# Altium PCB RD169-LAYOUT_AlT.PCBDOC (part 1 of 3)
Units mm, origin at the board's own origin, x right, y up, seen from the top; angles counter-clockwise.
Board outline 192 x 135 mm, 2 copper layers (TOP, BOTTOM), stack 0 mm thick; 266 components, 140 nets, 1304 pads, 0 vias.
Unrouted connection lines stored in the file: 1.
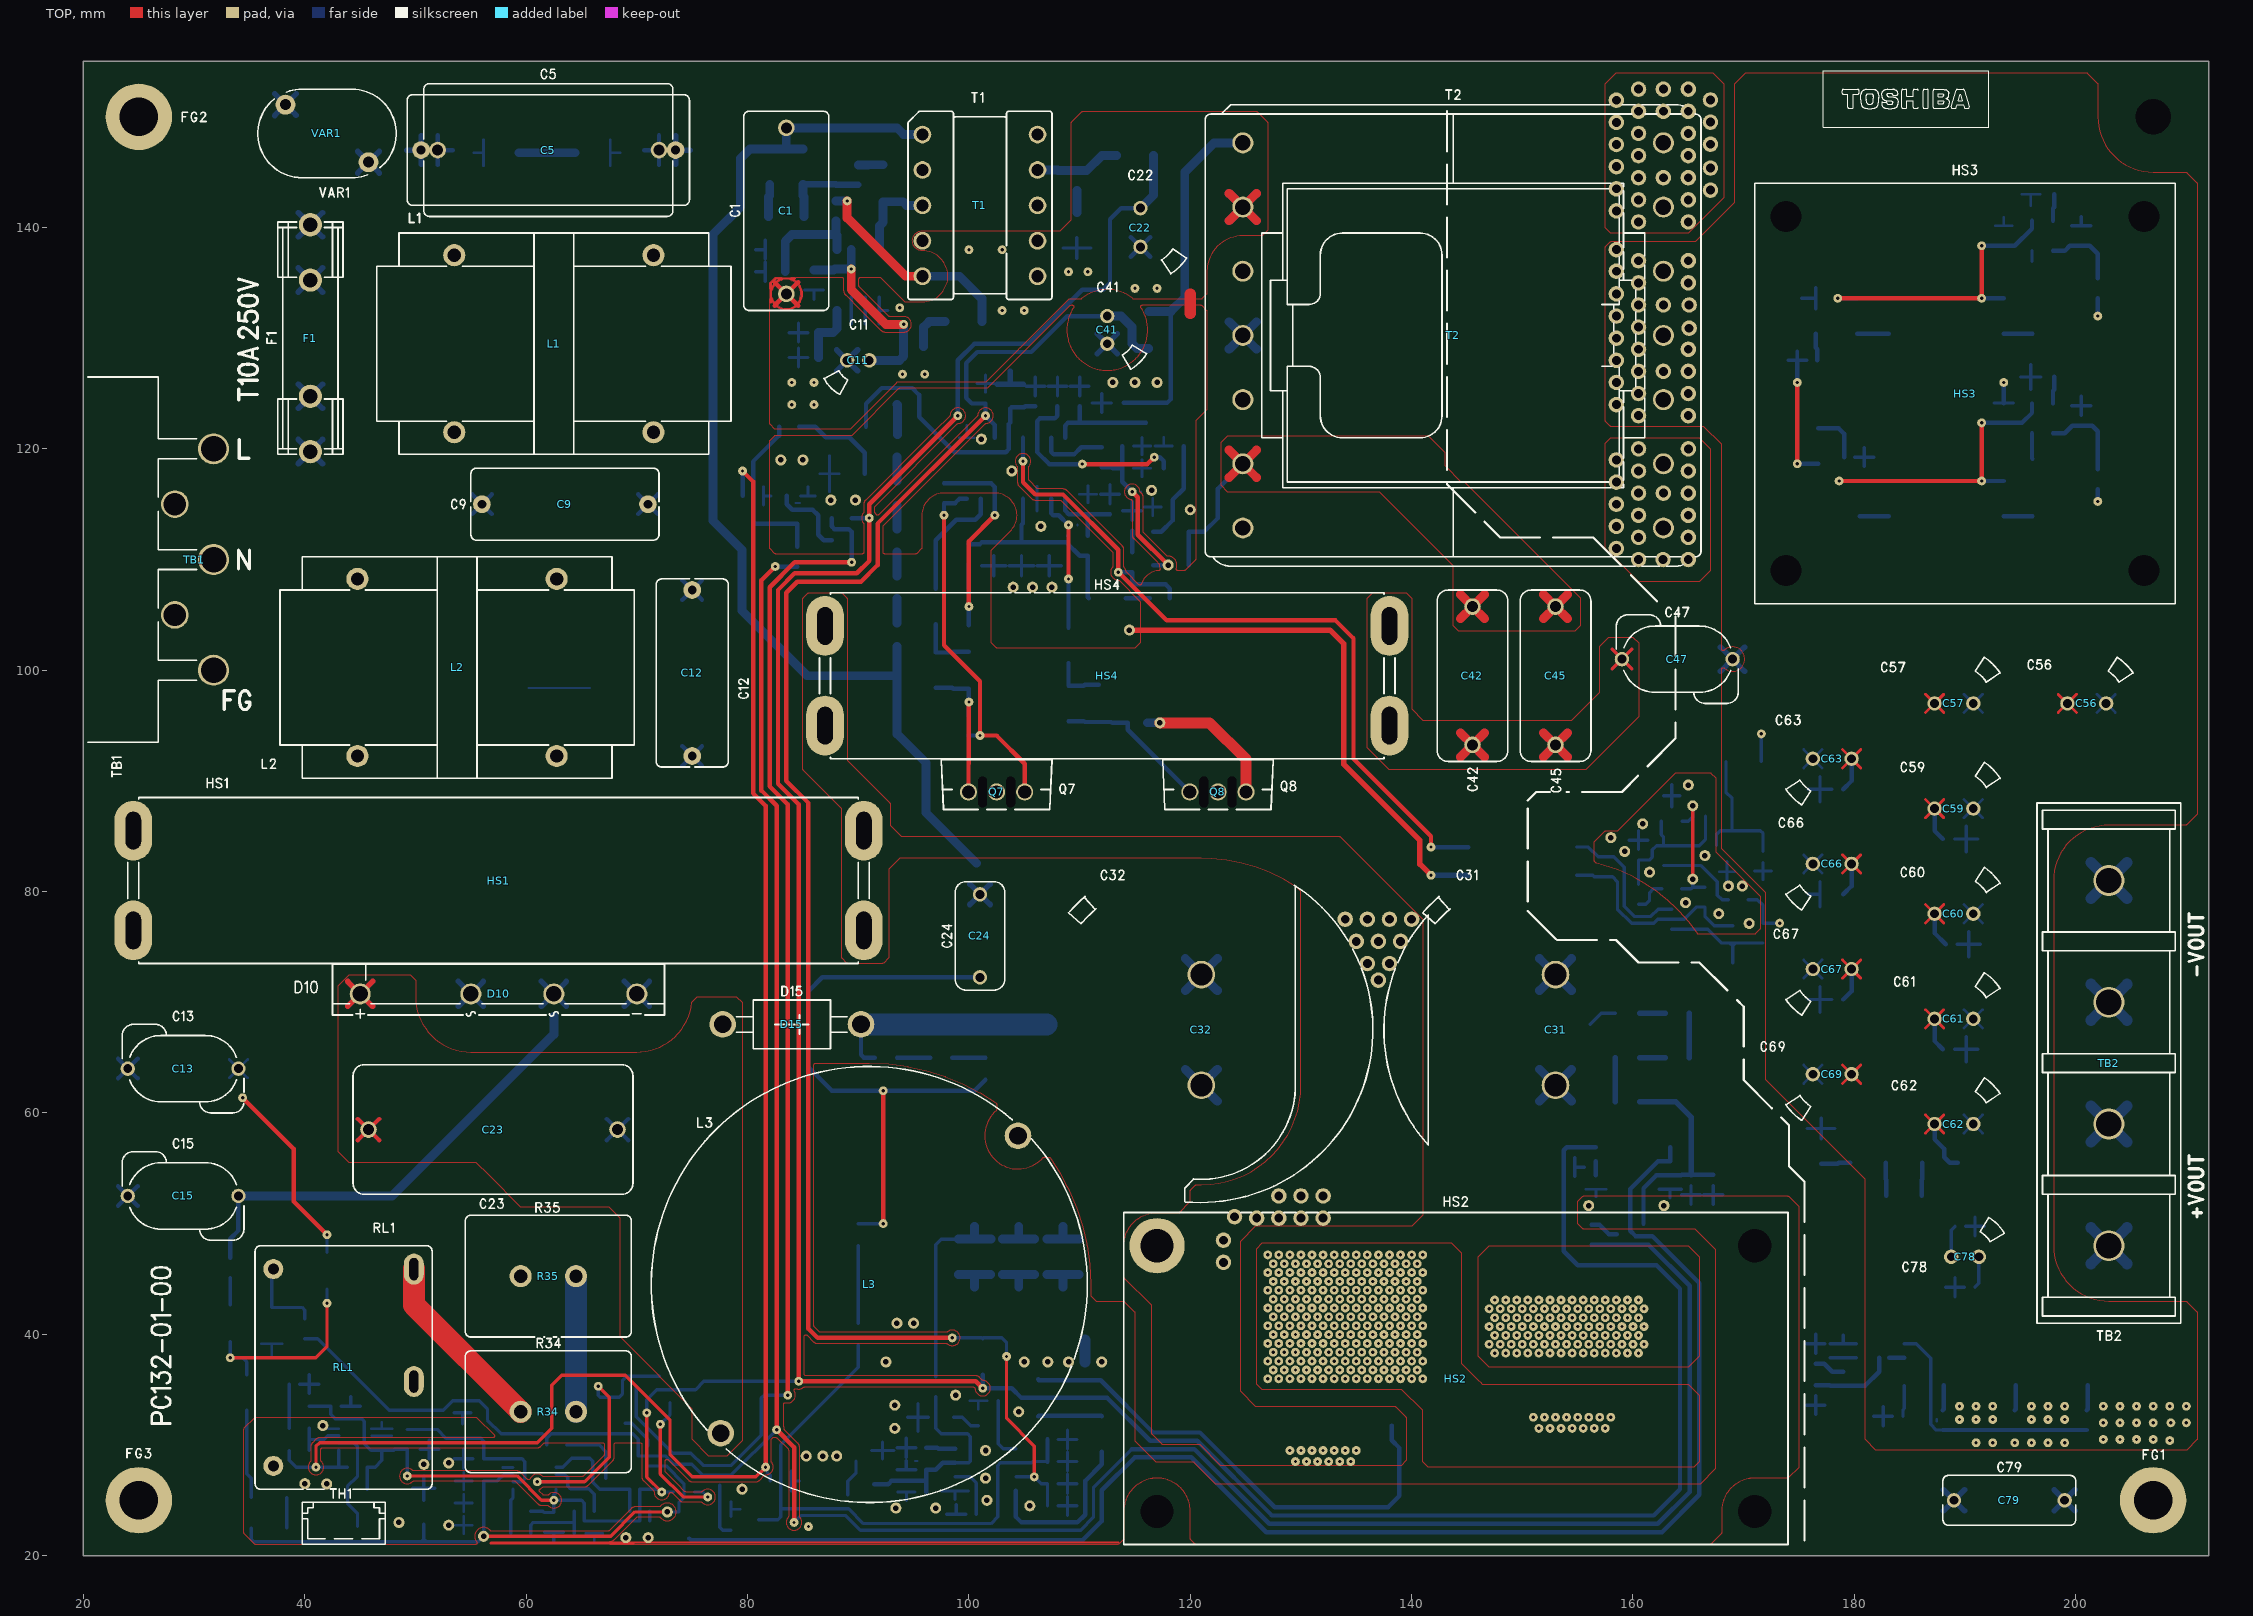
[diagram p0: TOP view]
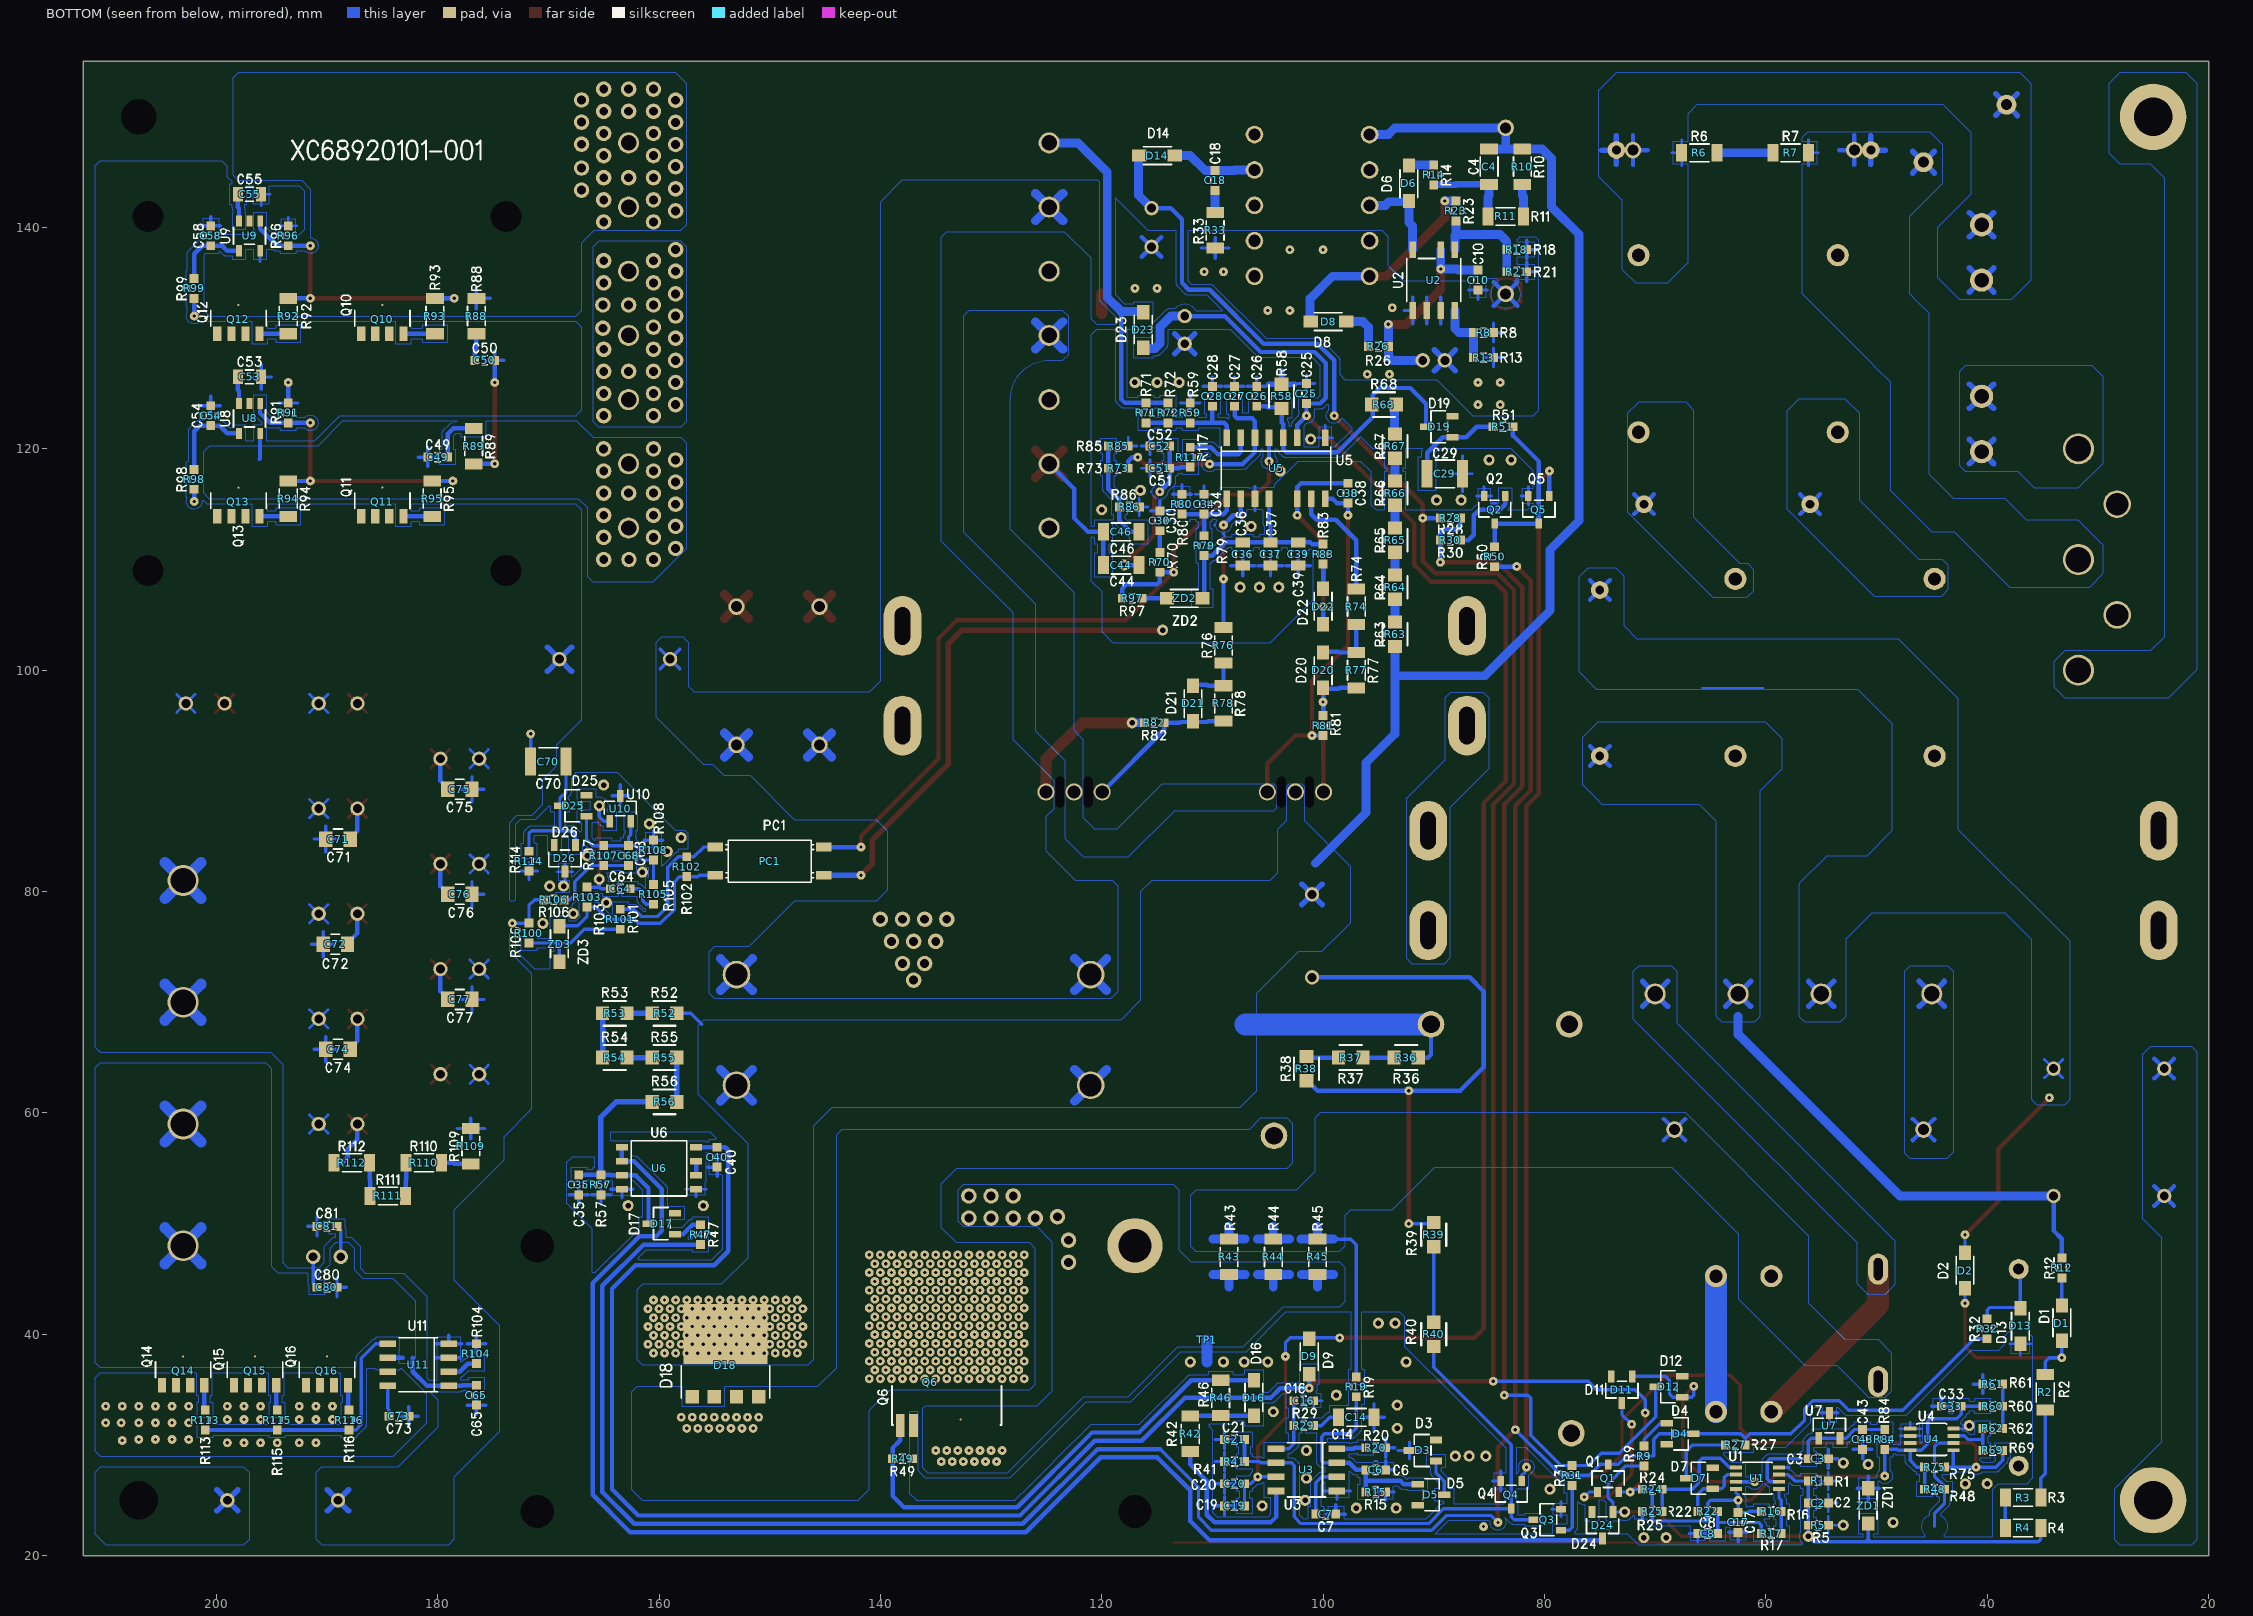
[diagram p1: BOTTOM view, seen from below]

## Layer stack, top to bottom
Top Solder: solder mask 0.0102, Solder Resist, Dk 3.5
TOP: signal copper (thickness not stored)
BOTTOM: signal copper (thickness not stored)
Bottom Solder: solder mask 0.0102, Solder Resist, Dk 3.5

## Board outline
212,20 20,20 20,155 212,155

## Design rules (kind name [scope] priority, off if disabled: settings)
AssemblyTestPointUsage [All] p0: scope1count=1 scope1_0_kind=Board scope1_0_value=Board scope2count=1 scope2_0_kind=Board scope2_0_value=Board commentlength=0
AssemblyTestpoint [All] p0: scope1count=1 scope1_0_kind=Board scope1_0_value=Board scope2count=1 scope2_0_kind=Board scope2_0_value=Board commentlength=0
Clearance [All] p0: scope1count=1 scope1_0_kind=Board scope1_0_value=Board scope2count=1 scope2_0_kind=Board scope2_0_value=Board commentlength=0 gap=0.001
Clearance [All] p1: gap=0.001 ignorepadtopadclearanceinfootprint=FALSE
ComponentClearance [All] p0: scope1count=1 scope1_0_kind=Board scope1_0_value=Board scope2count=1 scope2_0_kind=Board scope2_0_value=Board commentlength=0 gap=0.254 collisioncheckmode=3
DiffPairsRouting [All] p0: scope1count=1 scope1_0_kind=Board scope1_0_value=Board scope2count=1 scope2_0_kind=Board scope2_0_value=Board commentlength=0
FabricationTestPointUsage [All] p0: scope1count=1 scope1_0_kind=Board scope1_0_value=Board scope2count=1 scope2_0_kind=Board scope2_0_value=Board commentlength=0 valid=0 allowmultiple=FALSE
FabricationTestpoint [All] p0: scope1count=1 scope1_0_kind=Board scope1_0_value=Board scope2count=1 scope2_0_kind=Board scope2_0_value=Board commentlength=0 side=3 testpointundercomponent=TRUE minsize=1.016 maxsize=2.54 preferedsize=1.524 minholesize=0 maxholesize=1.016 preferedholesize=0.813 testpointgrid=0.025
FanoutControl Fanout_Default [All] p0: scope1count=1 scope1_0_kind=Board scope1_0_value=Board scope2count=1 scope2_0_kind=Board scope2_0_value=Board commentlength=30 // Fanout_Default (Default Rule)
FanoutControl Fanout_Small [All] p0 off: scope1count=1 scope1_0_kind=Board scope1_0_value=Board scope2count=1 scope2_0_kind=Board scope2_0_value=Board commentlength=84 // Protel DXP Scope 1 Expression Was: (CompPinCount < 5)   Fanout_Small (Default Rule)
FanoutControl Fanout_SOIC [All] p0 off: scope1count=1 scope1_0_kind=Board scope1_0_value=Board scope2count=1 scope2_0_kind=Board scope2_0_value=Board commentlength=71 // Protel DXP Scope 1 Expression Was: IsSOIC   Fanout_SOIC (Default Rule)
FanoutControl Fanout_LCC [All] p0 off: scope1count=1 scope1_0_kind=Board scope1_0_value=Board scope2count=1 scope2_0_kind=Board scope2_0_value=Board commentlength=69 // Protel DXP Scope 1 Expression Was: IsLCC   Fanout_LCC (Default Rule)
FanoutControl Fanout_BGA [All] p0 off: scope1count=1 scope1_0_kind=Board scope1_0_value=Board scope2count=1 scope2_0_kind=Board scope2_0_value=Board commentlength=69 // Protel DXP Scope 1 Expression Was: IsBGA   Fanout_BGA (Default Rule)
Height [All] p0: scope1count=1 scope1_0_kind=Board scope1_0_value=Board scope2count=1 scope2_0_kind=Board scope2_0_value=Board commentlength=0
HoleSize [All] p0: scope1count=1 scope1_0_kind=Board scope1_0_value=Board scope2count=1 scope2_0_kind=Board scope2_0_value=Board commentlength=0 absolutevalues=TRUE maxlimit=100 minlimit=0.001 maxpercent=80.000 minpercent=20.000
HoleSize [All] p1: absolutevalues=TRUE maxlimit=100 minlimit=0.001 maxpercent=80.000 minpercent=20.000
HoleToHoleClearance [All] p0: scope1count=1 scope1_0_kind=Board scope1_0_value=Board scope2count=1 scope2_0_kind=Board scope2_0_value=Board commentlength=0
HoleToHoleClearance [All] p1: gap=0.254 allowstackedmicrovias=FALSE
LayerPairs [All] p0: scope1count=1 scope1_0_kind=Board scope1_0_value=Board scope2count=1 scope2_0_kind=Board scope2_0_value=Board commentlength=0 enforce=TRUE
MinimumSolderMaskSliver [All] p0: scope1count=1 scope1_0_kind=Board scope1_0_value=Board scope2count=1 scope2_0_kind=Board scope2_0_value=Board commentlength=0
MinimumSolderMaskSliver [All] p1: minsoldermaskwidth=0.001
NetAntennae [All] p0: scope1count=1 scope1_0_kind=Board scope1_0_value=Board scope2count=1 scope2_0_kind=Board scope2_0_value=Board commentlength=0
NetAntennae [All] p1: netantennaetolerance=100
PasteMaskExpansion [All] p0: scope1count=1 scope1_0_kind=Board scope1_0_value=Board scope2count=1 scope2_0_kind=Board scope2_0_value=Board commentlength=0 expansion=0
PlaneClearance [All] p0: scope1count=1 scope1_0_kind=Board scope1_0_value=Board scope2count=1 scope2_0_kind=Board scope2_0_value=Board commentlength=0 clearance=0.001
PlaneClearance [All] p1: clearance=0.001
PlaneConnect [All] p0: scope1count=1 scope1_0_kind=Board scope1_0_value=Board scope2count=1 scope2_0_kind=Board scope2_0_value=Board commentlength=0 planeconnectstyle=Direct reliefexpansion=0.508 reliefentries=4 reliefconductorwidth=0.254 reliefairgap=0.254
PlaneConnect [All] p1: planeconnectstyle=Direct reliefexpansion=0.508 reliefentries=4 reliefconductorwidth=0.254 reliefairgap=0.254
PolygonConnect [All] p0: scope1count=1 scope1_0_kind=Board scope1_0_value=Board scope2count=1 scope2_0_kind=Board scope2_0_value=Board commentlength=0 connectstyle=Direct reliefconductorwidth=0.254 reliefentries=4 polygonreliefangle="90 Angle"
PolygonConnect [All] p1: connectstyle=Direct reliefconductorwidth=0.254 reliefentries=4 polygonreliefangle="90 Angle" airgapwidth=0.254
RoutingCorners [All] p0: scope1count=1 scope1_0_kind=Board scope1_0_value=Board scope2count=1 scope2_0_kind=Board scope2_0_value=Board commentlength=0 cornerstyle=45-Degree minsetback=2.54 maxsetback=2.54
RoutingLayers [All] p0: scope1count=1 scope1_0_kind=Board scope1_0_value=Board scope2count=1 scope2_0_kind=Board scope2_0_value=Board commentlength=0 top layer=Automatic bottom layer=Automatic
RoutingPriority [All] p0: scope1count=1 scope1_0_kind=Board scope1_0_value=Board scope2count=1 scope2_0_kind=Board scope2_0_value=Board commentlength=0
RoutingTopology [All] p0: scope1count=1 scope1_0_kind=Board scope1_0_value=Board scope2count=1 scope2_0_kind=Board scope2_0_value=Board commentlength=0 topology=Shortest
RoutingVias [All] p0: scope1count=1 scope1_0_kind=Board scope1_0_value=Board scope2count=1 scope2_0_kind=Board scope2_0_value=Board commentlength=0 holewidth=0.1 width=0.1 viastyle="Through Hole" minholewidth=0.001 minwidth=0.001 maxholewidth=100 maxwidth=100
RoutingVias [All] p1: holewidth=0.1 width=0.1 viastyle="Through Hole" minholewidth=0.001 minwidth=0.001 maxholewidth=100 maxwidth=100
ShortCircuit [All] p0: scope1count=1 scope1_0_kind=Board scope1_0_value=Board scope2count=1 scope2_0_kind=Board scope2_0_value=Board commentlength=0 allowed=FALSE
SilkToBoardRegionClearance [All] p0: scope1count=1 scope1_0_kind=Board scope1_0_value=Board scope2count=1 scope2_0_kind=Board scope2_0_value=Board commentlength=0
SilkToSilkClearance [All] p0: scope1count=1 scope1_0_kind=Board scope1_0_value=Board scope2count=1 scope2_0_kind=Board scope2_0_value=Board commentlength=0
SilkToSilkClearance [All] p1: silktosilkclearance=0.001
SilkToSolderMaskClearance [All] p0 off: scope1count=1 scope1_0_kind=Board scope1_0_value=Board scope2count=1 scope2_0_kind=Board scope2_0_value=Board commentlength=44 // Protel DXP Scope 1 Expression Was: IsPad
SilkToSolderMaskClearance [IsPad] p1: minsilkscreentomaskgap=0.001 clearancetoexposedcopper=TRUE
SolderMaskExpansion [All] p0: scope1count=1 scope1_0_kind=Board scope1_0_value=Board scope2count=1 scope2_0_kind=Board scope2_0_value=Board commentlength=0 expansion=0.001
SolderMaskExpansion [All] p1: expansion=0.001
UnRoutedNet [All] p0: scope1count=1 scope1_0_kind=Board scope1_0_value=Board scope2count=1 scope2_0_kind=Board scope2_0_value=Board commentlength=0
UnpouredPolygon [All] p0: scope1count=1 scope1_0_kind=Board scope1_0_value=Board scope2count=1 scope2_0_kind=Board scope2_0_value=Board commentlength=0
Width [All] p0: scope1count=1 scope1_0_kind=Board scope1_0_value=Board scope2count=1 scope2_0_kind=Board scope2_0_value=Board commentlength=0 maxlimit=1000 minlimit=2539.975 preferedwidth=0
Width [All] p1: maxlimit=1000 minlimit=2539.975 preferedwidth=0 toplayer_minwidth=0 bottomlayer_minwidth=0 minimp=50.000000 maximp=50.000000 favimp=50.000000
22 further rules are at their usual default settings.

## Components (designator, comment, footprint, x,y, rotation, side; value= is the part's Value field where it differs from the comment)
C1 "RD10010SP01" RD10010SP01 83.5,149 r270 top
C2 "KC00080SP01" KC00080SP01 55.25,24.75 r0 bottom
C3 "KC00080SP01" KC00080SP01 55.25,28.75 r0 bottom
C4 "KC00140SP01" KC00140SP01 85,145.5 r90 bottom
C5 "RD10180SP01" RD10180SP01 72,147 r180 top
C6 "KC00080SP01" KC00080SP01 95.25,27.75 r0 bottom
C7 "KC00080SP01" KC00080SP01 99.75,23.75 r0 bottom
C8 "KC00080SP01" KC00080SP01 65.25,22 r180 bottom
C9 "RD10370SP01" RD10370SP01 71,115 r180 top
C10 "KC00080SP01" KC00080SP01 86,135.25 r90 bottom
C11 "DC03410SP01" DC03410SP01 89,128 r0 top
C12 "RD10370SP01" RD10370SP01 75,92.25 r90 top
C13 "RD10380SP01" RD10380SP01 34,64 r180 top
C14 "KC00140SP01" KC00140SP01 97,32.5 r0 bottom
C15 "RD10380SP01" RD10380SP01 34,52.5 r180 top
C16 "KC00080SP01" KC00080SP01 101.75,34 r0 bottom
C17 "KC00080SP01" KC00080SP01 62.5,23 r90 bottom
C18 "KC00080SP01" KC00080SP01 109.75,144.25 r90 bottom
C19 "KC00080SP01" KC00080SP01 108,24.5 r180 bottom
C20 "KC00080SP01" KC00080SP01 108,26.5 r180 bottom
C21 "KC00080SP01" KC00080SP01 108,30.5 r180 bottom
C22 "RD10300SP01" RD10300SP01 115.5,138.25 r90 top
C23 "RD10460SP02" RD10460SP02 45.75,58.5 r0 top
C24 "RD10450SP01" RD10450SP01 101,79.75 r270 top
C25 "KC00080SP01" KC00080SP01 101.5,125 r270 bottom
C26 "KC00080SP01" KC00080SP01 106,124.75 r270 bottom
C27 "KC00080SP01" KC00080SP01 108,124.75 r270 bottom
C28 "KC00080SP01" KC00080SP01 110,124.75 r270 bottom
C29 "DC903A0SP01" DC903A0SP01 89,117.75 r0 bottom
C30 "KC00080SP01" KC00080SP01 114.75,113.5 r270 bottom
C31 "RD10210SP01" RD10210SP01 153,72.5 r270 top
C32 "RD10210SP01" RD10210SP01 121,72.5 r270 top
C33 "KC00080SP01" KC00080SP01 43.25,33.5 r180 bottom
C34 "KC00080SP01" KC00080SP01 110.75,115 r270 bottom
C35 "KC00080SP01" KC00080SP01 167.25,53.5 r90 bottom
C36 "KC00060SP02" KC00060SP02 107.25,110.5 r90 bottom
C37 "KC00060SP02" KC00060SP02 104.75,110.5 r90 bottom
C38 "KC00080SP01" KC00080SP01 97.75,116 r270 bottom
C39 "KC00060SP02" KC00060SP02 102.25,110.5 r90 bottom
C40 "KC00080SP01" KC00080SP01 154.75,56 r90 bottom
C41 "DC05080SP01" DC05080SP01 112.5,129.5 r90 top
C42 "RD10410SP01" RD10410SP01 145.5,105.75 r270 top
C43 "KC00080SP01" KC00080SP01 51.25,30.5 r90 bottom
C44 "KC00140SP01" KC00140SP01 118.25,109.5 r0 bottom
C45 "RD10410SP01" RD10410SP01 153,105.75 r270 top
C46 "KC00140SP01" KC00140SP01 118.25,112.5 r0 bottom
C47 "RD10380SP01" RD10380SP01 159,101 r0 top
C49 "KC00080SP01" KC00080SP01 180,119.25 r180 bottom
C50 "KC00080SP01" KC00080SP01 175.75,128 r180 bottom
C51 "KC00080SP01" KC00080SP01 114.75,118.25 r180 bottom
C52 "KC00080SP01" KC00080SP01 114.75,120.25 r180 bottom
C53 "KC00060SP02" KC00060SP02 197,126.5 r0 bottom
C54 "KC00080SP01" KC00080SP01 200.5,123 r270 bottom
C55 "KC00060SP02" KC00060SP02 197,143 r0 bottom
C56 "RD10300SP01" RD10300SP01 202.75,97 r180 top
C57 "RD10300SP01" RD10300SP01 190.75,97 r180 top
C58 "KC00080SP01" KC00080SP01 200.5,139.25 r270 bottom
C59 "RD10300SP01" RD10300SP01 190.75,87.5 r180 top
C60 "RD10300SP01" RD10300SP01 190.75,78 r180 top
C61 "RD10300SP01" RD10300SP01 190.75,68.5 r180 top
C62 "RD10300SP01" RD10300SP01 190.75,59 r180 top
C63 "RD10300SP01" RD10300SP01 176.25,92 r0 top
C64 "KC00080SP01" KC00080SP01 163.5,80.25 r180 bottom
C65 "KC00080SP01" KC00080SP01 176.5,34.5 r90 bottom
C66 "RD10300SP01" RD10300SP01 176.25,82.5 r0 top
C67 "RD10300SP01" RD10300SP01 176.25,73 r0 top
C68 "KC00080SP01" KC00080SP01 162.75,83.25 r270 bottom
C69 "RD10300SP01" RD10300SP01 176.25,63.5 r0 top
C70 "DC903A0SP01" DC903A0SP01 170,91.75 r0 bottom
C71 "KC00060SP01" KC00060SP01 189,84.75 r180 bottom
C72 "KC00060SP01" KC00060SP01 189.25,75.25 r180 bottom
C73 "KC00080SP01" KC00080SP01 183.5,32.6 r180 bottom
C74 "KC00060SP01" KC00060SP01 189,65.75 r180 bottom
C75 "KC00060SP01" KC00060SP01 178,89.25 r0 bottom
C76 "KC00060SP01" KC00060SP01 178,79.75 r0 bottom
C77 "KC00060SP01" KC00060SP01 178,70.25 r0 bottom
C78 "DC05080SP01" DC05080SP01 191.25,47 r180 top
C79 "RD10430SP01" RD10430SP01 199,25 r180 top
C80 "KC00080SP01" KC00080SP01 190,44.25 r180 bottom
C81 "KC00080SP01" KC00080SP01 190,49.75 r180 bottom
D1 "MMK01670SP01" MMK01670SP01 33.25,41 r90 bottom
D2 "MMK01670SP01" MMK01670SP01 42,45.75 r90 bottom
D3 "MM10240SP01" MM10240SP01 91,29.5 r270 bottom
D4 "MM10240SP01" MM10240SP01 67.75,31 r90 bottom
D5 "MM10240SP01" MM10240SP01 90.25,25.5 r90 bottom
D6 "MMK01670SP01" MMK01670SP01 92.25,144 r270 bottom
D7 "MM10240SP01" MM10240SP01 66,27 r270 bottom
D8 "MMK01670SP01" MMK01670SP01 99.5,131.5 r0 bottom
D9 "MMK01670SP01" MMK01670SP01 101.25,38 r270 bottom
D10 "D0001A0SP01" D0001A0SP01 45,70.75 r0 top
D11 "MM10240SP01" MM10240SP01 73,35 r180 bottom
D12 "MM10240SP01" MM10240SP01 68.75,35.25 r270 bottom
D13 "MMK01670SP01" MMK01670SP01 37,40.75 r270 bottom
D14 "MMK01670SP01" MMK01670SP01 115,146.5 r180 bottom
D15 "RD10400SP01" RD10400SP01 77.75,68 r0 top
D16 "MMK01670SP01" MMK01670SP01 106.25,34.25 r90 bottom
D17 "MM10240SP01" MM10240SP01 159.75,50 r270 bottom
D18 "MM11090SP01" MM11090SP01 154,38.25 r0 bottom
D19 "MM10240SP01" MM10240SP01 89.5,122 r270 bottom
D20 "MMK01670SP01" MMK01670SP01 100,100 r270 bottom
D21 "MMK01670SP01" MMK01670SP01 111.75,97 r270 bottom
D22 "MMK01670SP01" MMK01670SP01 100,105.75 r90 bottom
D23 "MMK01670SP01" MMK01670SP01 116.25,130.75 r90 bottom
D24 "MM10240SP01" MM10240SP01 74.75,22.75 r180 bottom
D25 "MM10240SP01" MM10240SP01 167.75,87.75 r270 bottom
D26 "MM10240SP01" MM10240SP01 168.5,83 r180 bottom
F1 "OD11240SP01" OD11240SP01 40.5,119.75 r90 top
HS1 "SE10220SP01" SE10220SP01 90.5,85.5 r180 top
HS2 "SE10240SP01" SE10240SP01 117,48 r0 top
HS3 "SE10160SP01" SE10160SP01 173.825,109 r0 top
HS4 "SE10230SP01" SE10230SP01 138,104 r180 top
L1 "OD11280SP01" OD11280SP01 53.5,137.5 r270 top
L2 "OD11280SP01" OD11280SP01 44.75,108.25 r270 top
L3 "OD11260SP01" OD11260SP01 77.565,31.065 r45 top
PC1 "MM11100SP01" MM11100SP01 150,82.75 r90 bottom
Q1 "DQ900A0SP01" DQ900A0SP01 74.25,27 r0 bottom
Q2 "DQ900A0SP01" DQ900A0SP01 84.5,114.5 r180 bottom
Q3 "DQ900A0SP01" DQ900A0SP01 79.75,23.25 r270 bottom
Q4 "DQ900A0SP01" DQ900A0SP01 83,25.5 r180 bottom
Q5 "DQ900A0SP01" DQ900A0SP01 80.5,114.5 r180 bottom
Q6 "MM11080SP01" MM11080SP01 134,37 r0 bottom
Q7 "SI10100SP01" SI10100SP01 99.96,89 r0 top
Q8 "SI10100SP01" SI10100SP01 119.96,89 r0 top
Q10 "SN00130SP01" SN00130SP01 185,133 r0 bottom
Q11 "SN00130SP01" SN00130SP01 185,116.5 r0 bottom
Q12 "SN00130SP01" SN00130SP01 198,133 r0 bottom
Q13 "SN00130SP01" SN00130SP01 198,116.5 r0 bottom
Q14 "SN00130SP01" SN00130SP01 203,38 r0 bottom
Q15 "SN00130SP01" SN00130SP01 196.5,38 r0 bottom
Q16 "SN00130SP01" SN00130SP01 190,38 r0 bottom
R1 "KC00080SP01" KC00080SP01 55.25,26.75 r0 bottom
R2 "KC00140SP01" KC00140SP01 34.75,34.75 r90 bottom
R3 "KC00140SP01" KC00140SP01 36.75,25.25 r180 bottom
R4 "KC00140SP01" KC00140SP01 36.75,22.5 r0 bottom
R5 "KC00080SP01" KC00080SP01 55.25,22.75 r0 bottom
R6 "KC00140SP01" KC00140SP01 66,146.75 r0 bottom
R7 "KC00140SP01" KC00140SP01 57.75,146.75 r0 bottom
R8 "KC00080SP01" KC00080SP01 85.5,130.5 r0 bottom
R9 "KC00080SP01" KC00080SP01 71,29 r270 bottom
R10 "KC00140SP01" KC00140SP01 82,145.5 r90 bottom
R11 "KC00140SP01" KC00140SP01 83.5,141 r180 bottom
R12 "KC00080SP01" KC00080SP01 33.25,46 r90 bottom
R13 "KC00080SP01" KC00080SP01 85.5,128.25 r0 bottom
R14 "KC00080SP01" KC00080SP01 90,144.75 r270 bottom
R15 "KC00080SP01" KC00080SP01 95.25,25.75 r0 bottom
R16 "KC00080SP01" KC00080SP01 59.5,24 r0 bottom
R17 "KC00080SP01" KC00080SP01 59.5,22 r180 bottom
R18 "KC00080SP01" KC00080SP01 82.5,138 r0 bottom
R19 "KC00080SP01" KC00080SP01 97,35.25 r90 bottom
R20 "KC00080SP01" KC00080SP01 95.25,29.75 r0 bottom
R21 "KC00080SP01" KC00080SP01 82.5,136 r0 bottom
R22 "KC00080SP01" KC00080SP01 65.25,24 r180 bottom
R23 "KC00080SP01" KC00080SP01 88,141.5 r90 bottom
R24 "KC00080SP01" KC00080SP01 70.25,26 r0 bottom
R25 "KC00080SP01" KC00080SP01 70.25,24 r180 bottom
R26 "KC00080SP01" KC00080SP01 95,129.25 r0 bottom
R27 "KC00080SP01" KC00080SP01 62.75,30 r0 bottom
R28 "KC00080SP01" KC00080SP01 88.5,113.75 r0 bottom
R29 "KC00080SP01" KC00080SP01 101.75,31.75 r0 bottom
R30 "KC00080SP01" KC00080SP01 88.5,111.75 r180 bottom
R31 "KC00080SP01" KC00080SP01 77.5,27.25 r270 bottom
R32 "KC00080SP01" KC00080SP01 40,40.5 r90 bottom
R33 "KC00140SP01" KC00140SP01 109.75,139.75 r90 bottom
R34 "OD11270SP01" OD11270SP01 64.5,33 r180 top
R35 "OD11270SP01" OD11270SP01 59.5,45.25 r0 top
R36 "KC00060SP03" KC00060SP03 92.5,65 r180 bottom
R37 "KC00060SP03" KC00060SP03 97.5,65 r180 bottom
R38 "KC00060SP03" KC00060SP03 101.5,64 r90 bottom
R39 "KC00060SP03" KC00060SP03 90,49 r90 bottom
R40 "KC00060SP03" KC00060SP03 90,40 r90 bottom
R41 "KC00080SP01" KC00080SP01 108,28.5 r180 bottom
R42 "KC00140SP01" KC00140SP01 112,31 r90 bottom
R43 "KC00140SP01" KC00140SP01 108.5,47 r90 bottom
R44 "KC00140SP01" KC00140SP01 104.5,47 r90 bottom
R45 "KC00140SP01" KC00140SP01 100.5,47 r90 bottom
R46 "KC00140SP01" KC00140SP01 109.25,34.25 r270 bottom
R47 "KC00080SP01" KC00080SP01 156.25,49 r270 bottom
R48 "KC00080SP01" KC00080SP01 44.75,26 r0 bottom
R49 "KC00080SP01" KC00080SP01 138,28.75 r180 bottom
R50 "KC00080SP01" KC00080SP01 84.5,110.25 r270 bottom
R51 "KC00080SP01" KC00080SP01 83.75,122 r0 bottom
R52 "KC00060SP03" KC00060SP03 159.5,69 r180 bottom
R53 "KC00060SP03" KC00060SP03 164,69 r180 bottom
R54 "KC00060SP03" KC00060SP03 164,65 r0 bottom
R55 "KC00060SP03" KC00060SP03 159.5,65 r0 bottom
R56 "KC00060SP03" KC00060SP03 159.5,61 r180 bottom
R57 "KC00080SP01" KC00080SP01 165.25,53.5 r90 bottom
R58 "KC00060SP03" KC00060SP03 103.75,124.75 r270 bottom
R59 "KC00080SP01" KC00080SP01 112,123.25 r270 bottom
R60 "KC00080SP01" KC00080SP01 39.5,33.5 r0 bottom
R61 "KC00080SP01" KC00080SP01 39.5,35.5 r180 bottom
R62 "KC00080SP01" KC00080SP01 39.5,31.5 r180 bottom
R63 "KC00060SP03" KC00060SP03 93.5,103.25 r270 bottom
R64 "KC00060SP03" KC00060SP03 93.5,107.5 r270 bottom
R65 "KC00060SP03" KC00060SP03 93.5,111.75 r270 bottom
R66 "KC00060SP03" KC00060SP03 93.5,116 r270 bottom
R67 "KC00060SP03" KC00060SP03 93.5,120.25 r270 bottom
R68 "KC00060SP03" KC00060SP03 94.5,124 r180 bottom
R69 "KC00080SP01" KC00080SP01 39.5,29.5 r0 bottom
R70 "KC00080SP01" KC00080SP01 114.75,109.75 r270 bottom
R71 "KC00080SP01" KC00080SP01 116,123.25 r90 bottom
R72 "KC00080SP01" KC00080SP01 114,123.25 r90 bottom
R73 "KC00080SP01" KC00080SP01 118.5,118.25 r180 bottom
R74 "KC00140SP01" KC00140SP01 97,105.75 r270 bottom
R75 "KC00080SP01" KC00080SP01 44.75,28 r0 bottom
R76 "KC00140SP01" KC00140SP01 109,102.25 r270 bottom
R77 "KC00140SP01" KC00140SP01 97,100 r90 bottom
R78 "KC00140SP01" KC00140SP01 109,97 r90 bottom
R79 "KC00080SP01" KC00080SP01 110.75,111.25 r270 bottom
R80 "KC00080SP01" KC00080SP01 112.75,115 r270 bottom
R81 "KC00080SP01" KC00080SP01 100,95 r90 bottom
R82 "KC00080SP01" KC00080SP01 115.25,95.25 r180 bottom
R83 "KC00080SP01" KC00080SP01 100,110.5 r270 bottom
R84 "KC00080SP01" KC00080SP01 49.25,30.5 r270 bottom
R85 "KC00080SP01" KC00080SP01 118.5,120.25 r0 bottom
R86 "KC00080SP01" KC00080SP01 117.5,114.75 r0 bottom
R88 "KC00140SP01" KC00140SP01 176.5,132 r90 bottom
R89 "KC00140SP01" KC00140SP01 176.75,120.25 r90 bottom
R91 "KC00080SP01" KC00080SP01 193.5,123.25 r90 bottom
R92 "KC00140SP01" KC00140SP01 193.5,132 r270 bottom
R93 "KC00140SP01" KC00140SP01 180.25,132 r270 bottom
R94 "KC00140SP01" KC00140SP01 193.5,115.5 r270 bottom
R95 "KC00140SP01" KC00140SP01 180.5,115.5 r270 bottom
R96 "KC00080SP01" KC00080SP01 193.5,139.25 r90 bottom
R97 "KC00080SP01" KC00080SP01 117.25,106.5 r0 bottom
R98 "KC00080SP01" KC00080SP01 202,117.25 r270 bottom
R99 "KC00080SP01" KC00080SP01 202,134.5 r90 bottom
R100 "KC00080SP01" KC00080SP01 171.75,76.25 r90 bottom
R101 "KC00080SP01" KC00080SP01 163.5,77.5 r270 bottom
R102 "KC00080SP01" KC00080SP01 157.5,82.25 r90 bottom
R103 "KC00080SP01" KC00080SP01 166.5,79.5 r270 bottom
R104 "KC00080SP01" KC00080SP01 176.5,38.25 r270 bottom
R105 "KC00080SP01" KC00080SP01 160.5,79.75 r270 bottom
R106 "KC00080SP01" KC00080SP01 169.5,79.25 r0 bottom
R107 "KC00080SP01" KC00080SP01 165,83.25 r270 bottom
R108 "KC00080SP01" KC00080SP01 160.5,83.75 r270 bottom
R109 "KC00140SP01" KC00140SP01 177,57 r90 bottom
R110 "KC00140SP01" KC00140SP01 181.25,55.5 r180 bottom
R111 "KC00140SP01" KC00140SP01 184.5,52.5 r180 bottom
R112 "KC00140SP01" KC00140SP01 187.75,55.5 r180 bottom
R113 "KC00080SP01" KC00080SP01 201,32.25 r90 bottom
R114 "KC00080SP01" KC00080SP01 171.75,82.75 r90 bottom
R115 "KC00080SP01" KC00080SP01 194.5,32.25 r90 bottom
R116 "KC00080SP01" KC00080SP01 188,32.25 r90 bottom
R117 "KC00080SP01" KC00080SP01 112,119.25 r90 bottom
RL1 "OD11250SP01" OD11250SP01 35.55,47.95 r270 top
T1 "OD11290SP01" OD11290SP01 95.8,148.4 r270 top
T2 "OD11300SP01" OD11300SP01 124.75,147.65 r270 top
TB1 "CT11580SP01" CT11580SP01 31.75,120 r270 top
TB2 "CU11710SP01" CU11710SP01 203,81 r270 top
TP1 "STAR2_SMT" STAR2_SMT 110.5,39.5 r0 bottom
U1 "I810E40SP01" I810E40SP01 60.75,27 r270 bottom
U2 "SP10390SP01" SP10390SP01 90,135.25 r0 bottom
U3 "SP00870SP01" SP00870SP01 101.5,27.75 r270 bottom
U4 "I810E40SP01" I810E40SP01 45,30.5 r270 bottom
U5 "SP10380SP01" SP10380SP01 104.25,118.25 r180 bottom
U6 "SP10370SP01" SP10370SP01 160,55 r90 bottom
U7 "MM10490SP01" MM10490SP01 54.25,31.75 r0 bottom
U8 "MM00630SP01" MM00630SP01 197,122.75 r180 bottom
U9 "MM00630SP01" MM00630SP01 197,139.25 r180 bottom
U10 "MM10490SP01" MM10490SP01 163.5,87.5 r0 bottom
U11 "SP00870SP01" SP00870SP01 181.75,37.25 r270 bottom
VAR1 "RD10440SP01" RD10440SP01 38.25,151.1 r0 top
ZD1 "MMK01670SP01" MMK01670SP01 50.75,24.5 r90 bottom
ZD2 "MMK01670SP01" MMK01670SP01 112.5,106.5 r0 bottom
ZD3 "MMK01670SP01" MMK01670SP01 169,75.25 r90 bottom

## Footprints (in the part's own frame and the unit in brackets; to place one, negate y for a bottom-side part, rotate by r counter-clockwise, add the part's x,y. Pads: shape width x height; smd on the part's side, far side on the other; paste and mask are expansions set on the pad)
CT11580SP01 [mm] "KC00080BKP"
  round 2.8 / inner round 0 / far side round 2.8 hole 2.3 paste-2.9 mask+0: 1(0,0) 2(10,0) 3(20,0)
  round 2.5 / inner round 0 / far side round 2.5 hole 2 paste-2.6 mask+0: 1T(5,-3.5) 2T(15,-3.5)
CU11710SP01 [mm] "KC00080BKP"
  round 2.8 / inner round 0 / far side round 2.8 hole 2.3 paste-2.9 mask+0: 1(0,0) 2(11,0) 3(22,0) 4(33,0)
D0001A0SP01 [mm] "KC00080BKP"
  round 1.9 / inner round 0 / far side round 1.9 hole 1.4 paste-2 mask+0: 1(0,0) 2(10,0) 3(17.5,0) 4(25,0)
DC903A0SP01 [mm] "KC00080BKP"
  rect 1x2.5 smd paste-2.5 mask+0: 1(1.6,0) 2(-1.6,0)
DC03410SP01 [mm] "KC00080BKP"
  round 1.3 / inner round 0 / far side round 1.3 hole 0.8 paste-1.4 mask+0: 1(0,0) 2(2,0)
DC05080SP01 [mm] "KC00080BKP"
  round 1.3 / inner round 0 / far side round 1.3 hole 0.8 paste-1.4 mask+0: 1(0,0) 2(2.5,0)
DQ900A0SP01 [mm] "KC00080BKP"
  rect 0.6x0.9 smd paste-0.9 mask+0: B(0.95,1.25) C(0,-1.25) E(-0.95,1.25)
I810E40SP01 [mm] "KC00080BKP"
  rect 0.35x1.1 smd paste-1.1 mask+0: 1(0.975,1.95) 2(0.325,1.95) 3(-0.325,1.95) 4(-0.975,1.95) 5(-0.975,-1.95) 6(-0.325,-1.95) 7(0.325,-1.95) 8(0.975,-1.95)
KC00060SP01 [mm] "KC00080BKP"
  rect 1.2x1.4 smd paste-1.4 mask+0: 1(1.1,0) 2(-1.1,0)
KC00060SP02 [mm] "KC00080BKP"
  rect 0.9x1.3 smd paste-1.3 mask+0: 1(1.05,0) 2(-1.05,0)
KC00060SP03 [mm] "KC00080BKP"
  rect 1.2x1.25 smd paste-1.25 mask+0: 1(1.1,0) 2(-1.1,0)
KC00080SP01 [mm] "KC00080BKP"
  rect 0.8x0.8 smd paste-0.8 mask+0: 1(0.9,0) 2(-0.9,0)
KC00140SP01 [mm] "KC00080BKP"
  rect 1x1.6 smd paste-1.6 mask+0: 1(1.6,0) 2(-1.6,0)
MM00630SP01 [mm] "KC00080BKP"
  rect 0.5x1 smd paste-1 mask+0: 1(0.95,1.35) 2(0,1.35) 3(-0.95,1.35) 4(-0.95,-1.35) 5(0.95,-1.35)
MM10240SP01 [mm] "KC00080BKP"
  rect 0.6x1.1 smd paste-1.1 mask+0: A(0,-1.2) C(0.95,1.2) NC(-0.95,1.2)
MM10490SP01 [mm] "KC00080BKP"
  rect 0.6x1.1 smd paste-1.1 mask+0: 1(0.95,1.15) 2(-0.95,1.15) 3(0,-1.15)
MM11080SP01 [mm] "KC00080BKP"
  rect 0.8x2.1 smd paste-2.1 mask+0: 1(4.2,5.24) 2(3,5.24)
  round 0.178 smd paste-0.178 mask+0: 3(-1.25,4.7) 9(0,-2.55)
MM11090SP01 [mm] "KC00080BKP"
  rect 1.2x1.2 smd paste-1.2 mask+0: 1(3,3.9) 2(1,3.9) 3(-1,3.9) 4(-3,3.9)
  rect 7.6x5.45 smd paste-7.6 mask+0: 5(0,-1.775)
MM11100SP01 [mm] "KC00080BKP"
  rect 0.8x1.4 smd paste-1.4 mask+0: A(1.27,4.9) C(1.27,-4.9) CA(-1.27,4.9) E(-1.27,-4.9)
MMK01670SP01 [mm] "KC00080BKP"
  rect 1.3x1.1 smd paste-1.3 mask+0: A(1.6,0) C(-1.6,0)
OD11240SP01 [mm] "KC00080BKP"
  round 2.1 / inner round 0 / far side round 2.1 hole 1.3 paste-2.2 mask+0: 1(0,0) 2(5,0) 3(15.5,0) 4(20.5,0)
OD11250SP01 [mm] "KC00080BKP"
  round 1.8 / inner round 0 / far side round 1.8 hole 1 paste-1.9 mask+0: 1(2.06,1.6) 2(19.84,1.6)
  oval 2.8x1.8 / inner round 0 / far side oval 2.8x1.8 hole 0.8 slot 2 at 0 deg paste-2.9 mask+0: 3(12.22,14.3) 4(2.06,14.3)
OD11260SP01 [mm] "KC00080BKP"
  round 2.4 / inner round 0 / far side round 2.4 hole 1.6 paste-2.5 mask+0: 1(0,0) 2(38,0)
OD11270SP01 [mm] "KC00080BKP"
  round 2 / inner round 0 / far side round 2 hole 1.2 paste-2.1 mask+0: 1(0,0) 2(5,0)
OD11280SP01 [mm] "KC00080BKP"
  round 2 / inner round 0 / far side round 2 hole 1.2 paste-2.1 mask+0: 1(0,0) 2(16,0) 3(16,18) 4(0,18)
OD11290SP01 [mm] "KC00080BKP"
  round 1.6 / inner round 0 / far side round 1.6 hole 1.1 paste-1.7 mask+0: 1(0,0) 2(3.2,0) 3(6.4,0) 4(9.6,0) 5(12.8,0) 6(12.8,10.4) 7(9.6,10.4) 8(6.4,10.4) 9(3.2,10.4) 10(0,10.4)
OD11300SP01 [mm] "KC00080BKP"
  round 1.9 / inner round 0 / far side round 1.9 hole 1.4 paste-2 mask+0: 1(0,0) 2(5.8,0) 3(11.6,0) 4(17.4,0) 5(23.2,0) 6(29,0) 7(34.8,0) 8(34.8,38) 9(29,38) 10(23.2,38) 11(17.4,38) 12(11.6,38) 13(5.8,38) 14(0,38)
RD10010SP01 [mm] "KC00080BKP"
  round 1.5 / inner round 0 / far side round 1.5 hole 1 paste-1.6 mask+0: 1(0,0) 2(15,0)
RD10180SP01 [mm] "KC00080BKP"
  round 1.5 / inner round 0 / far side round 1.5 hole 1 paste-1.6 mask+0: 1(0,0) 2(20,0)
RD10210SP01 [mm] "KC00080BKP"
  round 2.5 / inner round 0 / far side round 2.5 hole 2 paste-2.6 mask+0: 1(0,0) 2(10,0)
RD10300SP01 [mm] "KC00080BKP"
  round 1.3 / inner round 0 / far side round 1.3 hole 0.8 paste-1.4 mask+0: 1(0,0) 2(3.5,0)
RD10370SP01 [mm] "KC00080BKP"
  round 1.6 / inner round 0 / far side round 1.6 hole 0.8 paste-1.7 mask+0: 1(0,0) 2(15,0)
RD10380SP01 [mm] "KC00080BKP"
  round 1.3 / inner round 0 / far side round 1.3 hole 0.8 paste-1.4 mask+0: 1(0,0) 2(10,0)
RD10400SP01 [mm] "KC00080BKP"
  round 2.4 / inner round 0 / far side round 2.4 hole 1.6 paste-2.5 mask+0: A(0,0) C(12.5,0)
RD10410SP01 [mm] "KC00080BKP"
  round 1.5 / inner round 0 / far side round 1.5 hole 1 paste-1.6 mask+0: 1(0,0) 2(12.5,0)
RD10430SP01 [mm] "KC00080BKP"
  round 1.3 / inner round 0 / far side round 1.3 hole 0.8 paste-1.4 mask+0: 1(0,0) 2(10,0)
RD10440SP01 [mm] "KC00080BKP"
  round 1.8 / inner round 0 / far side round 1.8 hole 1 paste-1.9 mask+0: 1(0,0) 2(7.5,-5.2)
RD10450SP01 [mm] "KC00080BKP"
  round 1.3 / inner round 0 / far side round 1.3 hole 0.8 paste-1.4 mask+0: 1(0,0) 2(7.5,0)
RD10460SP02 [mm] "KC00080BKP"
  round 1.5 / inner round 0 / far side round 1.5 hole 1 paste-1.6 mask+0: 1(0,0) 2(22.5,0)
SE10160SP01 [mm] "KC00080BKP"
  round 0 hole 2.8 unplated paste-3 mask+0: 1T(0,0) 2T(32.35,0) 3T(32.35,32) 4T(0,32)
SE10220SP01 [mm] "KC00080BKP"
  oval 3.4x5.4 / inner round 0 / far side oval 3.4x5.4 hole 1.4 slot 3.4 at 90 deg paste-5.5 mask+0: 1T(0,0) 2T(0,9) 3T(66,0) 4T(66,9)
SE10230SP01 [mm] "KC00080BKP"
  oval 3.4x5.4 / inner round 0 / far side oval 3.4x5.4 hole 1.4 slot 3.4 at 90 deg paste-5.5 mask+0: 1T(0,0) 2T(0,9) 3T(51,0) 4T(51,9)
SE10240SP01 [mm] "KC00080BKP"
  round 5 / inner round 0 / far side round 5 hole 3 paste-5.1 mask+0: 1T(0,0)
  round 0 hole 3 unplated paste-3.5 mask+0: 2T(0,-24) 3T(54,-24) 4T(54,0)
SI10100SP01 [mm] "KC00080BKP"
  round 1.54 / inner round 0 / far side round 1.54 hole 1.2 paste-1.64 mask+0: D(2.54,0) G(0,0) S(5.08,0)
SN00130SP01 [mm] "KC00080BKP"
  rect 0.75x1.3 smd paste-1.3 mask+0: 1(1.905,2.6) 2(0.635,2.6) 3(-0.635,2.6) 4(-1.905,2.6)
  round 0.178 smd paste-0.178 mask+0: 5(0,0)
SP00870SP01 [mm] "KC00080BKP"
  rect 0.6x1.5 smd paste-1.5 mask+0: 1(1.905,2.75) 2(0.635,2.75) 3(-0.635,2.75) 4(-1.905,2.75) 5(-1.905,-2.75) 6(-0.635,-2.75) 7(0.635,-2.75) 8(1.905,-2.75)
SP10370SP01 [mm] "KC00080BKP"
  rect 0.6x1.1 smd paste-1.1 mask+0: 1(1.905,3.35) 2(0.635,3.35) 3(-0.635,3.35) 4(-1.905,3.35) 5(-1.905,-3.35) 6(-0.635,-3.35) 7(0.635,-3.35) 8(1.905,-3.35)
SP10380SP01 [mm] "KC00080BKP"
  rect 0.6x1.5 smd paste-1.5 mask+0: 1(4.445,2.75) 3(1.905,2.75) 4(0.635,2.75) 5(-0.635,2.75) 6(-1.905,2.75) 7(-3.175,2.75) 8(-4.445,2.75) 9(-4.445,-2.75) 10(-3.175,-2.75) 11(-1.905,-2.75) 12(-0.635,-2.75) 14(1.905,-2.75) 15(3.175,-2.75) 16(4.445,-2.75)
SP10390SP01 [mm] "KC00080BKP"
  rect 0.6x1.5 smd paste-1.5 mask+0: 1(1.905,2.75) 2(0.635,2.75) 3(-0.635,2.75) 4(-1.905,2.75) 5(-1.905,-2.75) 6(-0.635,-2.75) 8(1.905,-2.75)
STAR2_SMT [mm] "KC00080BKP"
  round 0.02 smd paste-0.02 mask+0: 1(0,0) 2(0,0)

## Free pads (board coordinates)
  round 6 / inner round 0 / far side round 6 hole 3.5 paste-6.1 mask+0: ""(25,25) ""(25,150)
  round 0.8 / inner round 0 / far side round 0.8 hole 0.3 paste-0.8 mask+0: ""(33.25,37.875) ""(34.375,61.375) ""(41,28) ""(42,42.8) ""(42,49) ""(49.25,27.2) ""(61,26.675) ""(62.5,25) ""(66.5,35.3) ""(70.9,32.9) ""(72.125,31.875) ""(72.25,25.75) ""(76.4,25.3) ""(79.55,118) ""(81.625,28) ""(82.5,109.375) ""(82.625,31.375) ""(83.625,34.5) ""(84,124) ""(84,126) ""(84.2,23) ""(84.625,35.75) ""(85.5,22.625) ""(86,124) ""(86,126) ""(89,142.4) ""(89.365,136.25) ""(89.4,109.75) ""(91,113.75) ""(92.25,50) ""(92.25,62) ""(93.75,132.75) ""(94,126.75) ""(94.1,131.25) ""(96,126.75) ""(97.75,114) ""(98.5,39.675) ""(99,123) ""(100,97.125) ""(100,105.75) ""(100,138) ""(101,94.1) ""(101.25,35.125) ""(101.5,123) ""(102.345,114) ""(103,132.5) ""(103,138) ""(103.4,38) ""(104.885,118.875) ""(105,132.5) ""(105.9,27.115) ""(109,108.25) ""(109,113.125) ""(109,136) ""(110.25,118.625) ""(110.75,136) ""(113.5,108.85) ""(114.75,116.125) ""(115,134.5) ""(116.75,119.25) ""(117,134.5) ""(127,35.975) ""(127,37.575) ""(127,39.175) ""(127,40.775) ""(127,42.375) ""(127,43.975) ""(127,45.575) ""(127,47.175) ""(127.5,36.775) ""(127.5,38.375) ""(127.5,39.975) ""(127.5,41.575) ""(127.5,43.175) ""(127.5,44.775) ""(127.5,46.375) ""(128,35.975) ""(128,37.575) ""(128,39.175) ""(128,40.775) ""(128,42.375) ""(128,43.975) ""(128,45.575) ""(128,47.175) ""(128.5,36.775) ""(128.5,38.375) ""(128.5,39.975) ""(128.5,41.575) ""(128.5,43.175) ""(128.5,44.775) ""(128.5,46.375) ""(129,29.5) ""(129,35.975) ""(129,37.575) ""(129,39.175) ""(129,40.775) ""(129,42.375) ""(129,43.975) ""(129,45.575) ""(129,47.175) ""(129.5,28.5) ""(129.5,36.775) ""(129.5,38.375) ""(129.5,39.975) ""(129.5,41.575) ""(129.5,43.175) ""(129.5,44.775) ""(129.5,46.375) ""(130,29.5) ""(130,35.975) ""(130,37.575) ""(130,39.175) ""(130,40.775) ""(130,42.375) ""(130,43.975) ""(130,45.575) ""(130,47.175) ""(130.5,28.5) ""(130.5,36.775) ""(130.5,38.375) ""(130.5,39.975) ""(130.5,41.575) ""(130.5,43.175) ""(130.5,44.775) ""(130.5,46.375) ""(131,29.5) ""(131,35.975) ""(131,37.575) ""(131,39.175) ""(131,40.775) ""(131,42.375) ""(131,43.975) ""(131,45.575) ""(131,47.175) ""(131.5,28.5) ""(131.5,36.775) ""(131.5,38.375) ""(131.5,39.975) ""(131.5,41.575) ""(131.5,43.175) ""(131.5,44.775) ""(131.5,46.375) ""(132,29.5) ""(132,35.975) ""(132,37.575) ""(132,39.175) ""(132,40.775) ""(132,42.375) ""(132,43.975) ""(132,45.575) ""(132,47.175) ""(132.5,28.5) ""(132.5,36.775) ""(132.5,38.375) ""(132.5,39.975) ""(132.5,41.575) ""(132.5,43.175) ""(132.5,44.775) ""(132.5,46.375) ""(133,29.5) ""(133,35.975) ""(133,37.575) ""(133,39.175) ""(133,40.775) ""(133,42.375) ""(133,43.975) ""(133,45.575) ""(133,47.175) ""(133.5,28.5) ""(133.5,36.775) ""(133.5,38.375) ""(133.5,39.975) ""(133.5,41.575) ""(133.5,43.175) ""(133.5,44.775) ""(133.5,46.375) ""(134,29.5) ""(134,35.975) ""(134,37.575) ""(134,39.175) ""(134,40.775) ""(134,42.375) ""(134,43.975) ""(134,45.575) ""(134,47.175) ""(134.5,28.5) ""(134.5,36.775) ""(134.5,38.375) ""(134.5,39.975) ""(134.5,41.575) ""(134.5,43.175) ""(134.5,44.775) ""(134.5,46.375) ""(135,29.5) ""(135,35.975) ""(135,37.575) ""(135,39.175) ""(135,40.775) ""(135,42.375) ""(135,43.975) ""(135,45.575) ""(135,47.175) ""(135.5,36.775) ""(135.5,38.375) ""(135.5,39.975) ""(135.5,41.575) ""(135.5,43.175) ""(135.5,44.775) ""(135.5,46.375) ""(136,35.975) ""(136,37.575) ""(136,39.175) ""(136,40.775) ""(136,42.375) ""(136,43.975) ""(136,45.575) ""(136,47.175) ""(136.5,36.775) ""(136.5,38.375) ""(136.5,39.975) ""(136.5,41.575) ""(136.5,43.175) ""(136.5,44.775) ""(136.5,46.375) ""(137,35.975) ""(137,37.575) ""(137,39.175) ""(137,40.775) ""(137,42.375) ""(137,43.975) ""(137,45.575) ""(137,47.175) ""(137.5,36.775) ""(137.5,38.375) ""(137.5,39.975) ""(137.5,41.575) ""(137.5,43.175) ""(137.5,44.775) ""(137.5,46.375) ""(138,35.975) ""(138,37.575) ""(138,39.175) ""(138,40.775) ""(138,42.375) ""(138,43.975) ""(138,45.575) ""(138,47.175) ""(138.5,36.775) ""(138.5,38.375) ""(138.5,39.975) ""(138.5,41.575) ""(138.5,43.175) ""(138.5,44.775) ""(138.5,46.375) ""(139,35.975) ""(139,37.575) ""(139,39.175) ""(139,40.775) ""(139,42.375) ""(139,43.975) ""(139,45.575) ""(139,47.175) ""(139.5,36.775) ""(139.5,38.375) ""(139.5,39.975) ""(139.5,41.575) ""(139.5,43.175) ""(139.5,44.775) ""(139.5,46.375) ""(140,35.975) ""(140,37.575) ""(140,39.175) ""(140,40.775) ""(140,42.375) ""(140,43.975) ""(140,45.575) ""(140,47.175) ""(140.5,36.775) ""(140.5,38.375) ""(140.5,39.975) ""(140.5,41.575) ""(140.5,43.175) ""(140.5,44.775) ""(140.5,46.375) ""(141,35.975) ""(141,37.575) ""(141,39.175) ""(141,40.775) ""(141,42.375) ""(141,43.975) ""(141,45.575) ""(141,47.175) ""(141.75,81.48) ""(141.75,84.02) ""(147,39.1) ""(147,40.7) ""(147,42.3) ""(147.5,38.3) ""(147.5,39.9) ""(147.5,41.5) ""(147.5,43.1) ""(148,39.1) ""(148,40.7) ""(148,42.3) ""(148.5,38.3) ""(148.5,39.9) ""(148.5,41.5) ""(148.5,43.1) ""(149,39.1) ""(149,40.7) ""(149,42.3) ""(149.5,38.3) ""(149.5,39.9) ""(149.5,41.5) ""(149.5,43.1) ""(150,39.1) ""(150,40.7) ""(150,42.3) ""(150.5,38.3) ""(150.5,39.9) ""(150.5,41.5) ""(150.5,43.1) ""(151,32.5) ""(151,39.1) ""(151,40.7) ""(151,42.3) ""(151.5,31.5) ""(151.5,38.3) ""(151.5,39.9) ""(151.5,41.5) ""(151.5,43.1) ""(152,32.5) ""(152,39.1) ""(152,40.7) ""(152,42.3) ""(152.5,31.5) ""(152.5,38.3) ""(152.5,39.9) ""(152.5,41.5) ""(152.5,43.1) ""(153,32.5) ""(153,39.1) ""(153,40.7) ""(153,42.3) ""(153.5,31.5) ""(153.5,38.3) ""(153.5,39.9) ""(153.5,41.5) ""(153.5,43.1) ""(154,32.5) ""(154,39.1) ""(154,40.7) ""(154,42.3) ""(154.5,31.5) ""(154.5,38.3) ""(154.5,39.9) ""(154.5,41.5) ""(154.5,43.1) ""(155,32.5) ""(155,39.1) ""(155,40.7) ""(155,42.3) ""(155.5,31.5) ""(155.5,38.3) ""(155.5,39.9) ""(155.5,41.5) ""(155.5,43.1) ""(156,32.5) ""(156,39.1) ""(156,40.7) ""(156,42.3) ""(156.5,31.5) ""(156.5,38.3) ""(156.5,39.9) ""(156.5,41.5) ""(156.5,43.1) ""(157,32.5) ""(157,39.1) ""(157,40.7) ""(157,42.3) ""(157.5,31.5) ""(157.5,38.3) ""(157.5,39.9) ""(157.5,41.5) ""(157.5,43.1) ""(158,32.5) ""(158,39.1) ""(158,40.7) ""(158,42.3) ""(158.5,38.3) ""(158.5,39.9) ""(158.5,41.5) ""(158.5,43.1) ""(159,39.1) ""(159,40.7) ""(159,42.3) ""(159.5,38.3) ""(159.5,39.9) ""(159.5,41.5) ""(159.5,43.1) ""(160,39.1) ""(160,40.7) ""(160,42.3) ""(160.5,38.3) ""(160.5,39.9) ""(160.5,41.5) ""(160.5,43.1) ""(161,39.1) ""(161,40.7) ""(161,42.3) ""(171.6,94.25) ""(173.25,77.15) ""(174.85,118.65) ""(174.85,126) ""(178.5,133.6) ""(178.625,117.1) ""(189.5,32.3) ""(189.5,33.5) ""(191,30.2) ""(191,32.3) ""(191,33.5) ""(191.5,117.1) ""(191.5,122.35) ""(191.5,133.6) ""(191.5,138.35) ""(192.5,30.2) ""(192.5,32.3) ""(192.5,33.5) ""(193.5,126) ""(194.5,30.2) ""(196,30.2) ""(196,32.3) ""(196,33.5) ""(197.5,30.2) ""(197.5,32.3) ""(197.5,33.5) ""(199,30.2) ""(199,32.3) ""(199,33.5) ""(202,115.25) ""(202,132) ""(202.5,30.5) ""(202.5,32) ""(202.5,33.5) ""(204,30.5) ""(204,32) ""(204,33.5) ""(205.5,30.5) ""(205.5,32) ""(205.5,33.5) ""(207,30.5) ""(207,32) ""(207,33.5) ""(208.5,30.4) ""(208.5,33.5) ""(208.6,32) ""(210,32) ""(210,33.5)
  round 1 / inner round 0 / far side round 1 hole 0.5 paste-1 mask+0: ""(40,26.5) ""(41.625,31.75) ""(41.975,26.475) ""(48.5,23) ""(50.75,28.25) ""(53,22.75) ""(53,28.375) ""(56.15,21.75) ""(69,21.625) ""(71.025,21.625) ""(72.75,23.95) ""(79.5,26) ""(83,119) ""(85,119) ""(85.3,29) ""(86.8,29) ""(87.525,115.375) ""(88.05,29) ""(89.75,115.375) ""(92.5,37.5) ""(93.3,31.5) ""(93.3,33.6) ""(93.4,24.3) ""(93.5,41) ""(95,41) ""(97,24.3) ""(98.8,34.5) ""(101.125,120.875) ""(101.5,27) ""(101.5,29.5) ""(101.625,25) ""(103.875,118.002) ""(104,107.5) ""(104.5,33) ""(105,37.5) ""(105.5,24.5) ""(105.75,107.5) ""(106.5,113) ""(107.125,37.5) ""(107.5,107.5) ""(109,37.5) ""(112,37.5) ""(113,126) ""(114.5,103.625) ""(115,126) ""(116.5,116.25) ""(117,126) ""(117.25,95.25) ""(118,109.5) ""(120,114.5) ""(156,51.625) ""(158,84.875) ""(159.25,83.625) ""(160.875,86.125) ""(161.5,81.75) ""(162.8,51.625) ""(164.75,79) ""(165,89.625) ""(165.4,81.125) ""(165.4,87.75) ""(166.5,83.25) ""(167.75,78) ""(168.625,80.5) ""(169.875,80.5) ""(170.5,77.125)
  round 1.6 / inner round 0 / far side round 1.6 hole 0.8 paste-1.7 mask+0: ""(50.5,147) ""(73.5,147)
  round 0 hole 0.8 slot 2.8 at 90 deg unplated paste-3.05 mask+0: ""(101.23,89) ""(103.77,89) ""(121.23,89) ""(123.77,89)
  round 1.4 / inner round 0 / far side round 1.4 hole 0.8 paste-1.4 mask+0: ""(123,46.5) ""(123,48.5) ""(124,50.625) ""(126,50.5) ""(128,50.5) ""(128,52.5) ""(130,50.5) ""(130,52.5) ""(132,50.5) ""(132,52.5) ""(134,77.5) ""(135,75.5) ""(136,73.5) ""(136,77.5) ""(137,72) ""(137,75.5) ""(138,73.5) ""(138,77.5) ""(139,75.5) ""(140,77.5) ""(158.5,111) ""(158.5,113) ""(158.5,115) ""(158.5,117) ""(158.5,119) ""(158.5,124) ""(158.5,126) ""(158.5,128) ""(158.5,130) ""(158.5,132) ""(158.5,134) ""(158.5,136.05) ""(158.5,138) ""(158.5,141.5) ""(158.5,143.5) ""(158.5,145.5) ""(158.5,147.5) ""(158.5,149.5) ""(158.5,151.5) ""(160.5,110) ""(160.5,112) ""(160.5,114) ""(160.5,116) ""(160.5,118) ""(160.5,120) ""(160.5,123) ""(160.5,125) ""(160.5,127) ""(160.5,129) ""(160.5,131) ""(160.5,133) ""(160.5,135) ""(160.5,137) ""(160.5,140.5) ""(160.5,142.5) ""(160.5,144.5) ""(160.5,146.5) ""(160.5,148.5) ""(160.5,150.5) ""(160.5,152.5) ""(162.716,109.999) ""(162.75,116) ""(162.75,127) ""(162.75,133) ""(162.75,144.5) ""(162.75,150.5) ""(162.75,152.5) ""(165,110) ""(165,112) ""(165,114) ""(165,116) ""(165,118) ""(165,123) ""(165,125) ""(165,127) ""(165,129) ""(165,135) ""(165,137) ""(165,140.5) ""(165,142.5) ""(165,144.5) ""(165,146.5) ""(165,148.5) ""(165,150.5) ""(165,152.5) ""(165.01,119.995) ""(165.071,130.901) ""(165.071,133) ""(167,143.375) ""(167,145.375) ""(167,147.525) ""(167,149.525) ""(167,151.525)
  round 6 smd paste-6 mask+0: ""(207,25) ""(207,25)
  round 0 hole 3.5 paste-3.5 mask+0: ""(207,25)
  round 0 hole 3.2 unplated paste-3.5 mask+0: ""(207,150)

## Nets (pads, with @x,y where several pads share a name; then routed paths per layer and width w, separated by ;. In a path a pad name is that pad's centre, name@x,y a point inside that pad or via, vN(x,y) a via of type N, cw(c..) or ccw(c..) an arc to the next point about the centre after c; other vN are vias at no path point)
12VREC: C56.2 C57.2 C59.2 C60.2 C61.2 C62.2 C63.2 C66.2 C67.2 C69.2 C70.1 C71.1 C72.1 C73.1 C74.1 C75.1 C76.1 C77.1 pad.@158.5,124 pad.@158.5,126 pad.@158.5,128 pad.@158.5,130 pad.@158.5,132 pad.@158.5,134 pad.@158.5,136.05 pad.@158.5,138 pad.@160.5,123 pad.@160.5,125 pad.@160.5,127 pad.@160.5,129 pad.@160.5,131 pad.@160.5,133 pad.@160.5,135 pad.@160.5,137 pad.@162.75,127 pad.@162.75,133 pad.@165,123 pad.@165,125 pad.@165,127 pad.@165,129 pad.@165,135 pad.@165,137 pad.@165.071,130.901 pad.@165.071,133 pad.@171.6,94.25 pad.@173.25,77.15 pad.@189.5,32.3 pad.@189.5,33.5 pad.@191,30.2 pad.@191,32.3 pad.@191,33.5 pad.@192.5,30.2 pad.@192.5,32.3 pad.@192.5,33.5 pad.@194.5,30.2 pad.@196,30.2 pad.@196,32.3 pad.@196,33.5 pad.@197.5,30.2 pad.@197.5,32.3 pad.@197.5,33.5 pad.@199,30.2 pad.@199,32.3 pad.@199,33.5 pad.@202,115.25 pad.@202,132 pad.@202.5,30.5 pad.@202.5,32 pad.@202.5,33.5 pad.@204,30.5 pad.@204,32 pad.@204,33.5 pad.@205.5,30.5 pad.@205.5,32 pad.@205.5,33.5 pad.@207,30.5 pad.@207,32 pad.@207,33.5 pad.@208.5,30.4 pad.@208.5,33.5 pad.@208.6,32 pad.@210,32 pad.@210,33.5 Q14.1 Q14.2 Q14.3 Q15.1 Q15.2 Q15.3 Q16.1 Q16.2 Q16.3 R98.1 R99.2 R100.1 R106.1 R112.2 T2.10 T2.11 T2.12 U11.7 | length 83.7
  TOP w0.25: 178.919,62.669 C69.2@179.75,63.5 ; 178.919,64.331 C69.2@179.75,63.5 ; 178.919,72.169 C67.2@179.75,73 ; 178.919,73.831 C67.2@179.75,73 ; 178.919,81.669 C66.2@179.75,82.5 ; 178.919,83.331 C66.2@179.75,82.5 ; 178.919,91.169 C63.2@179.75,92 ; 178.919,92.831 C63.2@179.75,92 ; 180.581,62.669 C69.2@179.75,63.5 ; 180.581,64.331 C69.2@179.75,63.5 ; 180.581,72.169 C67.2@179.75,73 ; 180.581,73.831 C67.2@179.75,73 ; 180.581,81.669 C66.2@179.75,82.5 ; 180.581,83.331 C66.2@179.75,82.5 ; 180.581,91.169 C63.2@179.75,92 ; 180.581,92.831 C63.2@179.75,92 ; 186.419,58.169 C62.2@187.25,59 ; 186.419,59.831 C62.2@187.25,59 ; 186.419,67.669 C61.2@187.25,68.5 ; 186.419,69.331 C61.2@187.25,68.5 ; 186.419,77.169 C60.2@187.25,78 ; 186.419,78.831 C60.2@187.25,78 ; 186.419,86.669 C59.2@187.25,87.5 ; 186.419,88.331 C59.2@187.25,87.5 ; 186.419,96.169 C57.2@187.25,97 ; 186.419,97.831 C57.2@187.25,97 ; 188.081,58.169 C62.2@187.25,59 ; 188.081,59.831 C62.2@187.25,59 ; 188.081,67.669 C61.2@187.25,68.5 ; 188.081,69.331 C61.2@187.25,68.5 ; 188.081,77.169 C60.2@187.25,78 ; 188.081,78.831 C60.2@187.25,78 ; 188.081,86.669 C59.2@187.25,87.5 ; 188.081,88.331 C59.2@187.25,87.5 ; 188.081,96.169 C57.2@187.25,97 ; 188.081,97.831 C57.2@187.25,97 ; 198.419,96.169 C56.2@199.25,97 ; 198.419,97.831 C56.2@199.25,97 ; 200.081,96.169 C56.2@199.25,97 ; 200.081,97.831 C56.2@199.25,97
  BOTTOM w0.2: 187.45,32.15 187.45,32.35
  BOTTOM w0.3: R106.1@170.4,79.25 171.25,79.25 171.75,78.75 R100.1@171.75,77.15 pad.@173.25,77.15 ; C70.1@171.6,91.75 pad.@171.6,94.25 ; 181.75,32.6 C73.1@182.6,32.6 ; 182.6,31.75 C73.1@182.6,32.6 ; 182.6,33.45 C73.1@182.6,32.6 ; 183.45,32.6 C73.1@182.6,32.6
  BOTTOM w0.4: C77.1@179,70.25 179.75,71 C67.2@179.75,73 ; C76.1@179,79.75 179.05,79.8 179.75,80.5 C66.2@179.75,82.5 ; C75.1@179,89.25 179.75,90 C63.2@179.75,92 ; C62.2@187.25,59 187.25,57.625 188.125,56.75 188.125,56 188.625,55.5 R112.2@189.35,55.5 ; C61.2@187.25,68.5 187.25,66.5 187.95,65.8 C74.1@188,65.75 ; C60.2@187.25,78 187.25,76.25 C72.1@188.25,75.25 ; C59.2@187.25,87.5 187.25,85.5 187.95,84.8 C71.1@188,84.75 ; pad.@202,115.25 R98.1@202,116.35 ; pad.@202,132 R99.2@202,133.6
+HV: C1.1 C4.1 C24.1 C31.2 C32.2 D15.C D18.5 pad.@147,39.1 pad.@147,40.7 pad.@147,42.3 pad.@147.5,38.3 pad.@147.5,39.9 pad.@147.5,41.5 pad.@147.5,43.1 pad.@148,39.1 pad.@148,40.7 pad.@148,42.3 pad.@148.5,38.3 pad.@148.5,39.9 pad.@148.5,41.5 pad.@148.5,43.1 pad.@149,39.1 pad.@149,40.7 pad.@149,42.3 pad.@149.5,38.3 pad.@149.5,39.9 pad.@149.5,41.5 pad.@149.5,43.1 pad.@150,39.1 pad.@150,40.7 pad.@150,42.3 pad.@150.5,38.3 pad.@150.5,39.9 pad.@150.5,41.5 pad.@150.5,43.1 pad.@151,39.1 pad.@151,40.7 pad.@151,42.3 pad.@151.5,38.3 pad.@151.5,39.9 pad.@151.5,41.5 pad.@151.5,43.1 pad.@152,39.1 pad.@152,40.7 pad.@152,42.3 pad.@152.5,38.3 pad.@152.5,39.9 pad.@152.5,41.5 pad.@152.5,43.1 pad.@153,39.1 pad.@153,40.7 pad.@153,42.3 pad.@153.5,38.3 pad.@153.5,39.9 pad.@153.5,41.5 pad.@153.5,43.1 pad.@154,39.1 pad.@154,40.7 pad.@154,42.3 pad.@154.5,38.3 pad.@154.5,39.9 pad.@154.5,41.5 pad.@154.5,43.1 pad.@155,39.1 pad.@155,40.7 pad.@155,42.3 pad.@155.5,38.3 pad.@155.5,39.9 pad.@155.5,41.5 pad.@155.5,43.1 pad.@156,39.1 pad.@156,40.7 pad.@156,42.3 pad.@156.5,38.3 pad.@156.5,39.9 pad.@156.5,41.5 pad.@156.5,43.1 pad.@157,39.1 pad.@157,40.7 pad.@157,42.3 pad.@157.5,38.3 pad.@157.5,39.9 pad.@157.5,41.5 pad.@157.5,43.1 pad.@158,39.1 pad.@158,40.7 pad.@158,42.3 pad.@158.5,38.3 pad.@158.5,39.9 pad.@158.5,41.5 pad.@158.5,43.1 pad.@159,39.1 pad.@159,40.7 pad.@159,42.3 pad.@159.5,38.3 pad.@159.5,39.9 pad.@159.5,41.5 pad.@159.5,43.1 pad.@160,39.1 pad.@160,40.7 pad.@160,42.3 pad.@160.5,38.3 pad.@160.5,39.9 pad.@160.5,41.5 pad.@160.5,43.1 pad.@161,39.1 pad.@161,40.7 pad.@161,42.3 Q7.D R10.1 R36.1 R52.1 R63.1 T1.1 | length 145.5
  BOTTOM w0.3: 156.125,68 157.125,69 R52.1@158.4,69
  BOTTOM w0.4: D15.C@90.25,68 90.25,65.25 90.5,65 R36.1@91.4,65 R36.1@91.5,65
  BOTTOM w0.5: 100.081,78.831 C24.1@101,79.75 ; 100.081,80.669 C24.1@101,79.75 ; 101.919,78.831 C24.1@101,79.75 ; 101.919,80.669 C24.1@101,79.75
  BOTTOM w0.8: C4.1@85,147.1 83.5,147.1 ; R63.1@93.5,102.15 93.5,99.5 ; T1.1@95.8,148.4 94.1,148.4 93.5,149 C1.1@83.5,149 83.5,147.1 ; 100.688,82.563 96.125,87.125 96.125,91.625 93.5,94.25 93.5,99.5 ; 119.55,63.95 C32.2@121,62.5 ; 122.45,61.05 C32.2@121,62.5 ; 122.45,63.95 C32.2@121,62.5 ; 151.55,61.05 C31.2@153,62.5 ; 151.55,63.95 C31.2@153,62.5 ; 154.45,61.05 C31.2@153,62.5 ; 154.45,63.95 C31.2@153,62.5 ; 83.5,147.1 R10.1@82,147.1 80.225,147.1 79.375,146.25 79.375,141.875 76.875,139.375 76.875,113.5 79.5,110.875 79.5,105.375 85.375,99.5 93.5,99.5
  BOTTOM w2: D15.C@90.25,68 107,68
ACinREC: D1.C D2.C pad.@33.25,37.875 pad.@42,42.8 R2.1 | length 18.6
  TOP w0.3: pad.@33.25,37.875 41,37.875 42,38.875 pad.@42,42.8
  BOTTOM w0.3: D1.C@33.25,39.325 pad.@33.25,37.875 34.375,37.875 34.75,37.5 R2.1@34.75,36.35 ; pad.@42,42.8 D2.C@42,44.075
ACinVDET1: D11.A pad.@72.125,31.875 pad.@76.4,25.3 Q1.B | length 13.3
  TOP w0.3: pad.@72.125,31.875 72.125,27.375 74.2,25.3 pad.@76.4,25.3
  BOTTOM w0.3: pad.@72.125,31.875 73,32.75 D11.A@73,33.8 ; Q1.B@75.2,25.75 75.95,25.75 pad.@76.4,25.3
